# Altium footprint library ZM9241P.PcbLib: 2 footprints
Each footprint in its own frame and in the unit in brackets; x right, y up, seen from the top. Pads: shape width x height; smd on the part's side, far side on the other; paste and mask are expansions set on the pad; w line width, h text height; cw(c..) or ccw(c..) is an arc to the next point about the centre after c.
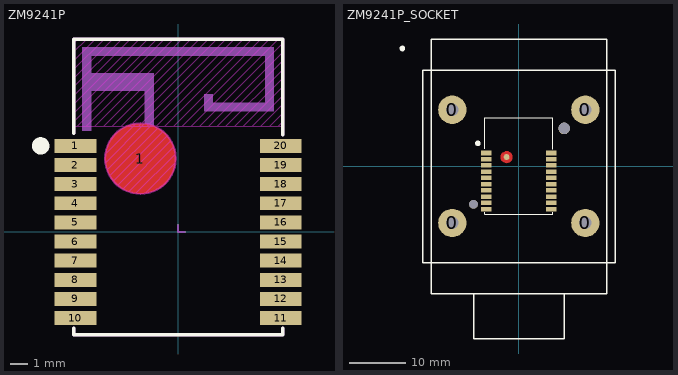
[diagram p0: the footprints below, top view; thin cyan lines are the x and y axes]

## ZM9241P [mm] "ZM9241P Rev.A"
height 2.6
pads (21):
  rect 2.4x0.8 smd mask+0.051: 1(-5.9,4.95) 2(-5.9,3.85) 3(-5.9,2.75) 4(-5.9,1.65) 5(-5.9,0.55) 6(-5.9,-0.55) 7(-5.9,-1.65) 8(-5.9,-2.75) 9(-5.9,-3.85) 10(-5.9,-4.95) 11(5.9,-4.95) 12(5.9,-3.85) 13(5.9,-2.75) 14(5.9,-1.65) 15(5.9,-0.55) 16(5.9,0.55) 17(5.9,1.65) 18(5.9,2.75) 19(5.9,3.85) 20(5.9,4.95)
  round 1.016 on Mech15 paste-0.508 mask+0.381: 1(-2.168,4.221)
Top Layer:
  pour cut-out: -4.208,4.221 -4.169,3.823 -4.053,3.44 -3.864,3.088 -3.61,2.779 -3.301,2.525 -2.949,2.336 -2.566,2.22 -2.168,2.181 -1.77,2.22 -1.388,2.336 -1.035,2.525 -0.726,2.779 -0.472,3.088 -0.284,3.44 -0.167,3.823 -0.128,4.221 -0.167,4.619 -0.284,5.002 -0.472,5.354 -0.726,5.663 -1.035,5.917 -1.388,6.106 -1.77,6.222 -2.168,6.261 -2.566,6.222 -2.949,6.106 -3.301,5.917 -3.61,5.663 -3.864,5.354 -4.053,5.002 -4.169,4.619
Top Layer keep-out:
  circle w0.127: c-2.168,4.221 r2.03
  lines w0.025: -4.169,3.992 -1.922,6.238 ; -4.162,4.5 -2.429,6.234 ; -4.075,3.584 -1.504,6.155 ; -3.924,3.233 -1.156,6 ; -3.736,2.918 -0.865,5.789 ; -3.485,2.667 -0.614,5.538 ; -3.183,2.467 -0.411,5.239 ; -2.842,2.306 -0.256,4.892 ; -2.432,2.214 -0.147,4.498 ; -1.96,2.183 -0.13,4.013
Top Overlay:
  circle w0.5: c-7.9,4.95 r0.25
  lines w0.2: -6,-5.54 -6,-5.91 6,-5.91 6,-5.54 ; -6,5.661 -6,11.09 6,11.09 6,5.585
Keep-Out Layer:
  lines w0.025: -5.999,6.334 -1.243,11.09 ; -5.998,6.837 -1.745,11.09 ; -5.998,7.339 -2.248,11.09 ; -5.998,7.841 -2.75,11.09 ; -5.998,8.344 -3.252,11.09 ; -5.998,8.846 -3.754,11.09 ; -5.998,9.348 -4.256,11.09 ; -5.998,9.85 -4.758,11.09 ; -5.998,10.352 -5.26,11.09 ; -5.998,10.854 -5.763,11.09 ; -5.787,6.09 -0.787,11.09 ; -5.284,6.09 -0.285,11.09 ; -4.782,6.09 0.218,11.09 ; -4.28,6.09 0.72,11.09 ; -3.778,6.09 1.222,11.09 ; -3.276,6.09 1.724,11.09 ; -2.774,6.09 2.226,11.09 ; -2.272,6.09 2.728,11.09 ; -1.77,6.09 3.23,11.09 ; -1.267,6.09 3.733,11.09 ; -0.765,6.09 4.235,11.09 ; -0.263,6.09 4.737,11.09 ; 0.239,6.09 5.241,11.092 ; 0.741,6.09 5.741,11.089 ; 1.243,6.09 5.999,10.846 ; 1.745,6.09 5.998,10.343 ; 2.248,6.09 5.998,9.841 ; 2.75,6.09 5.998,9.339 ; 3.252,6.09 5.998,8.836 ; 3.754,6.09 5.998,8.334 ; 4.256,6.09 5.998,7.832 ; 4.758,6.09 5.998,7.33 ; 5.26,6.09 5.998,6.828 ; 5.763,6.09 5.998,6.326 ; -6,6.09 6,6.09 6,11.09 -6,11.09 -6,6.09
Mechanical 15:
  region: -5.505,5.808 -5.005,5.808 -5.005,8.128 -1.905,8.128 -1.905,5.603 -1.405,5.603 -1.405,9.128 -5.005,9.128 -5.005,10.128 4.995,10.128 4.995,7.428 1.995,7.428 1.995,7.926 1.495,7.926 1.495,6.928 5.495,6.928 5.495,10.628 -5.505,10.628
  lines w0.114: 0,0.4 0,0 0.4,0
  lines w0.2: -6,-5.54 -6,-5.91 6,-5.91 6,-5.54 ; -6,5.661 -6,11.09 6,11.09 6,5.585
  text "各层禁止走线" at -0.635,8.229 h0.76
  text "天线区域" at -0.635,9.017 h0.76

## ZM9241P_SOCKET [mm] "ZM9241P_SOCKET"
pads (27):
  round 5 hole 2.2: 0(-11.75,-10) 0(-11.75,10) 0(11.75,-10) 0(11.75,10)
  rect 1.9x0.8 smd paste-1.27 mask+0.051: 1(-5.75,2.36) 2(-5.75,1.26) 3(-5.75,0.16) 4(-5.75,-0.94) 5(-5.75,-2.04) 6(-5.75,-3.14) 7(-5.75,-4.24) 8(-5.75,-5.34) 9(-5.75,-6.44) 10(-5.75,-7.54) 11(5.75,-7.54) 12(5.75,-6.44) 13(5.75,-5.34) 14(5.75,-4.24) 15(5.75,-3.14) 16(5.75,-2.04) 17(5.75,-0.94) 18(5.75,0.16) 19(5.75,1.26) 20(5.75,2.36)
  round 1.016 smd paste-0.508 mask+0.381: 21(-2.159,1.651)
  round 1.53 hole 1.53 unplated: ""(-8,-6.7)
  round 2.03 hole 2.03 unplated: ""(8,6.7)
Top Layer:
  pour cut-out: -1.116,1.623 -1.152,1.351 -1.257,1.098 -1.424,0.88 -1.642,0.713 -1.895,0.608 -2.167,0.573 -2.439,0.608 -2.692,0.713 -2.909,0.88 -3.076,1.098 -3.181,1.351 -3.217,1.623 -3.181,1.895 -3.076,2.148 -2.909,2.366 -2.692,2.533 -2.439,2.638 -2.167,2.673 -1.895,2.638 -1.642,2.533 -1.424,2.366 -1.257,2.148 -1.152,1.895
Top Overlay:
  circle w0.5: c-20.57,20.828 r0.25
  circle w0.5: c-7.239,4.064 r0.25
  lines w0.2: -6,-8.08 -6,-8.446 6,-8.446 6,-8.08 ; -6,3.121 -6,8.554 6,8.554 6,3.045
  lines w0.254: -15.5,-8.5 -15.5,-22.5 ; -8,-22.5 -8,-30.5 8,-30.5 8,-22.501 ; -15.5,-22.5 15.5,-22.5 15.5,22.5 -15.5,22.5 -15.5,-22.5 ; -17,-17 17,-17 17,17 -17,17 -17,-17
Top Solder:
  lines w1.118: -3.046,2.698 ccw(c-2.159,1.651) -1.274,2.698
